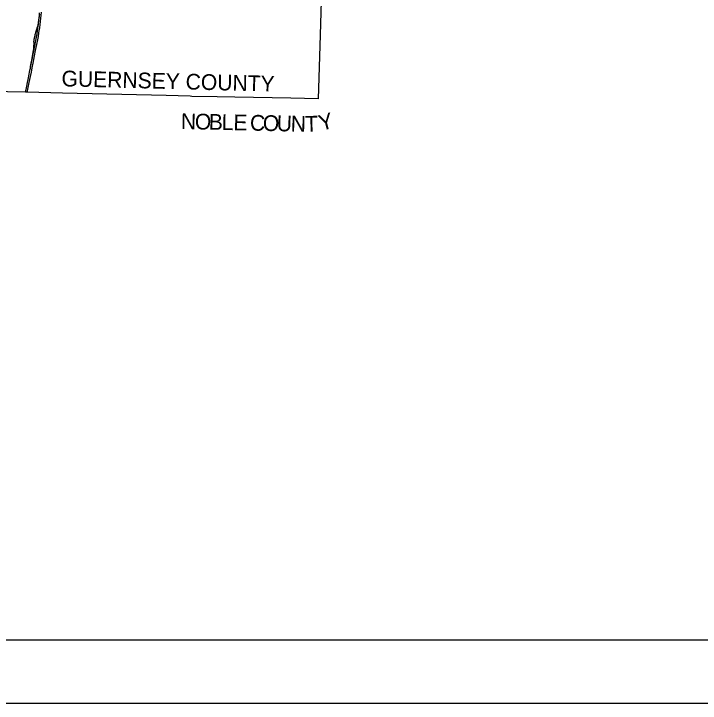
# Model space of a CAD drawing. Extents: x 2125567 to 2397567, y 653347 to 829347.
# Drawn here: x 2239770 to 2283311, y 653347 to 697090 of the extents above; entities that cross this region are included whole.
import ezdxf

# ---------------------------------------------------------------- set-up
doc = ezdxf.new("R2010")
doc.units = 0
for name, color, linetype in [('GM_X_County', 7, 'Continuous'), ('GM_X_County_Text', 7, 'Continuous'), ('SH_Border', 7, 'Continuous'), ('SH_Cut_Line', 7, 'Continuous'), ('UT_P_Electric', 7, 'Continuous')]:
    doc.layers.add(name, color=color, linetype=linetype)

msp = doc.modelspace()

# ---------------------------------------------------------------- linework, layer by layer
at = {"layer": 'GM_X_County'}
msp.add_lwpolyline([(2259393, 702239), (2259194, 695727), (2259077, 691693), (2257342, 691741), (2253798, 691790), (2252665, 691829), (2251071, 691852), (2250968, 691854), (2249437, 691909), (2242864, 692063), (2240626, 692108), (2240515, 692110), (2237090, 692186)], dxfattribs=at)
at = {"layer": 'SH_Border'}
msp.add_lwpolyline([(2137567, 825347), (2393567, 825347), (2393567, 657347), (2137567, 657347)], close=True, dxfattribs=at)
at = {"layer": 'SH_Cut_Line'}
msp.add_lwpolyline([(2125567, 653347), (2397567, 653347), (2397567, 829347), (2125567, 829347)], close=True, dxfattribs=at)
at = {"layer": 'UT_P_Electric'}
for points in [[(2240516, 692107), (2240575, 692401), (2240639, 692726), (2240679, 692926), (2240746, 693270), (2240795, 693511), (2240820, 693641), (2240840, 693740), (2240903, 694058), (2240948, 694287), (2240986, 694480), (2241018, 694637), (2241080, 694953), (2241168, 695397), (2241207, 695610), (2241245, 695829), (2241270, 695982), (2241301, 696193), (2241332, 696420), (2241346, 696534), (2241378, 696834), (2241393, 696988), (2241400, 697071), (2241407, 697161)], [(2240627, 692105), (2240666, 692303), (2240731, 692624), (2240789, 692914), (2240825, 693101), (2240883, 693390), (2240936, 693661), (2240995, 693963), (2241086, 694417), (2241156, 694767), (2241229, 695137), (2241290, 695446), (2241329, 695659), (2241365, 695872), (2241386, 696005), (2241412, 696190), (2241440, 696401), (2241463, 696593), (2241485, 696808), (2241503, 696991), (2241519, 697191)], [(2241400, 697071), (2241392, 697047), (2241387, 697032), (2241383, 697017), (2241379, 696999), (2241375, 696975), (2241370, 696939), (2241356, 696786), (2241341, 696659), (2241332, 696590), (2241315, 696500), (2241294, 696400), (2241265, 696283), (2241239, 696191), (2241208, 696088), (2241191, 696034), (2241145, 695894), (2241126, 695828), (2241111, 695757), (2241097, 695687), (2241049, 695449), (2241033, 695365), (2241030, 695342), (2241030, 695319), (2241032, 695264), (2241033, 695218), (2241032, 695165), (2241028, 695073), (2241022, 694979), (2241012, 694874), (2241001, 694780), (2240980, 694643), (2240962, 694540), (2240934, 694385), (2240874, 694046), (2240842, 693862), (2240840, 693845), (2240838, 693825), (2240835, 693781), (2240835, 693773), (2240836, 693761), (2240837, 693749), (2240840, 693740)]]:
    msp.add_lwpolyline(points, dxfattribs=at)

# ---------------------------------------------------------------- texts
at = {"layer": 'GM_X_County_Text'}
for s, rotation, p in [('GUERNSEY COUNTY', 358.543, (2242786, 692493)), ('N', 358.7336, (2250362, 689778)), ('O', 358.7341, (2251246, 689758)), ('B', 358.7334, (2252130, 689739)), ('L', 358.7341, (2252944, 689721)), ('Y', 14.2636, (2259251, 689652)), ('E', 358.7335, (2253692, 689704)), ('C', 358.7334, (2254743, 689681)), ('O', 358.7341, (2255557, 689663)), ('U', 358.7325, (2256441, 689643)), ('N', 358.9045, (2257329, 689624)), ('T', 0.9353, (2258252, 689607))]:
    msp.add_text(s, height=1000, rotation=rotation, dxfattribs=at).set_placement(p)

doc.saveas('drawing.dxf')
